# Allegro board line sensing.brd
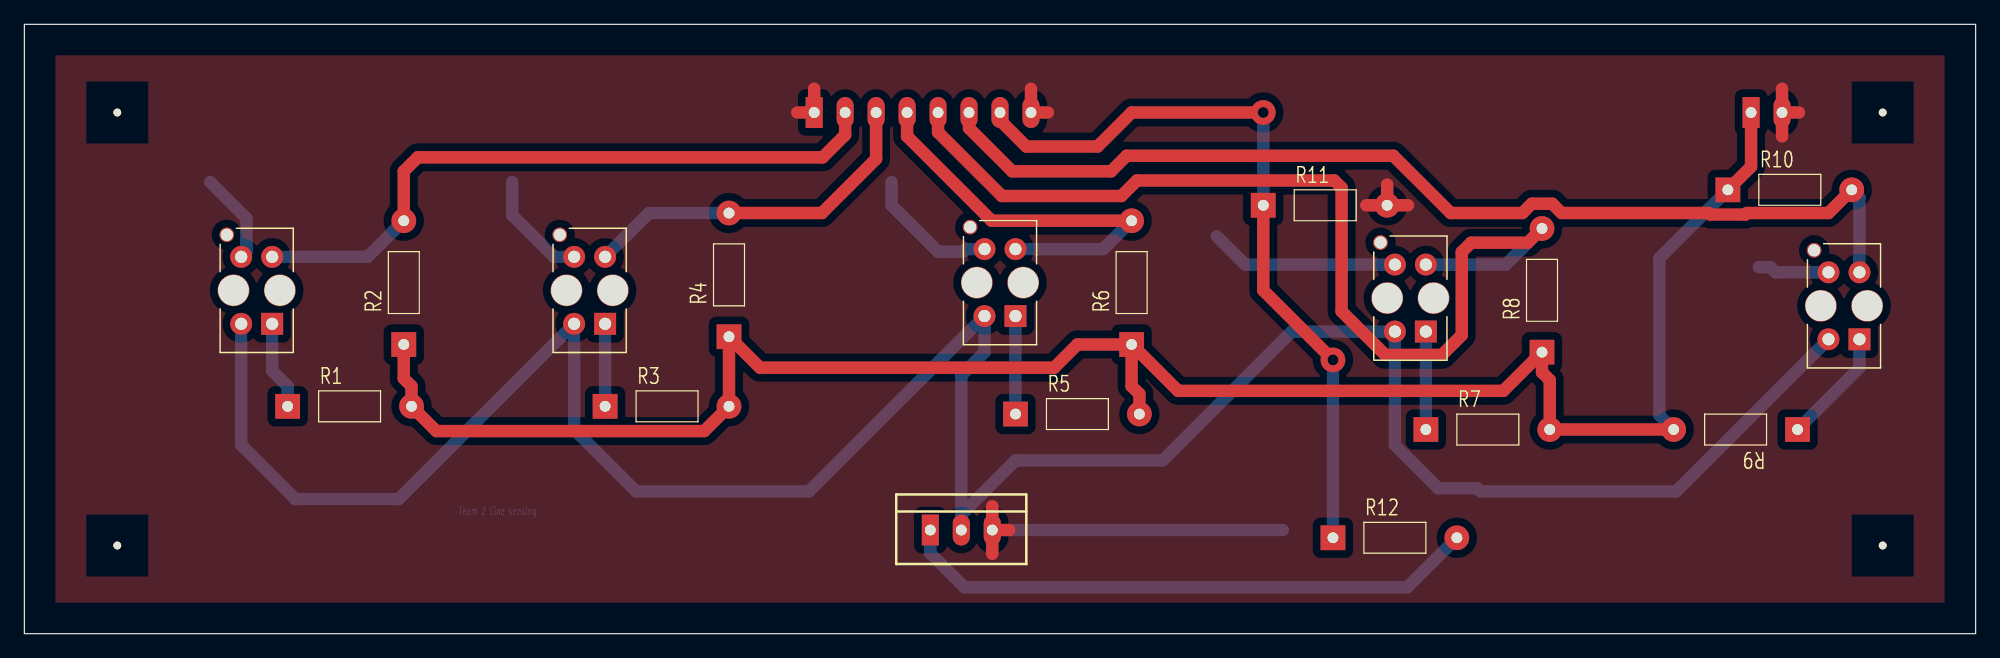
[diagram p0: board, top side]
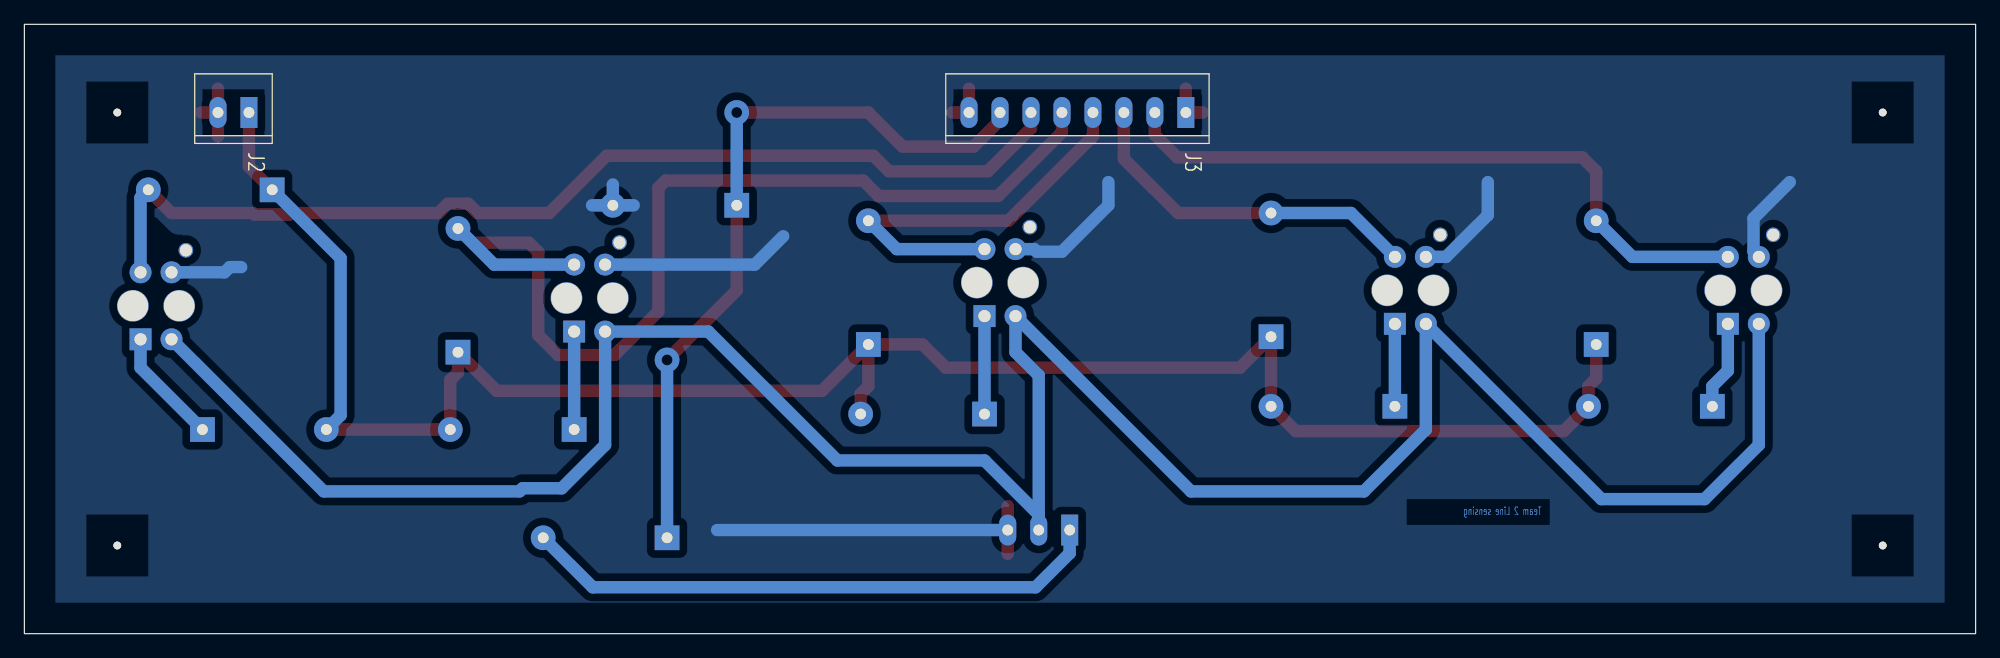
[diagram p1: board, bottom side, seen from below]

Outline 160.02 x 50.04 mm; copper layers: TOP, BOTTOM. Coordinates in mm from the lower left corner of the outline.
Outline path: rectangle 0,0 160.02,50.04

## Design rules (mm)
constraint set DEFAULT: min track width 1.016

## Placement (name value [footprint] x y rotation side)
J2  Power  [GU-MOLEX2]  141.61 42.8 270 bottom
J3  CON8  [GU-MOLEX8]  64.77 42.8 270 bottom
NOREF  -  [unnamed]  7.62 42.8 0 top
NOREF#2  -  [unnamed]  152.4 42.8 0 top
NOREF#3  -  [unnamed]  152.4 7.24 0 top
NOREF#4  -  [unnamed]  7.62 7.24 0 top
Q1  TIP121  [GU-TO220AB]  74.3 8.51 0 top
R1  200  [GU-RC400]  21.59 18.67 0 top
R2  10K  [GU-RC400]  31.12 23.75 90 top
R3  200  [GU-RC400]  47.63 18.67 0 top
R4  10K  [GU-RC400]  57.79 24.38 90 top
R5  200  [GU-RC400]  81.28 18.03 0 top
R6  10K  [GU-RC400]  90.81 23.75 90 top
R7  200  [GU-RC400]  114.94 16.76 0 top
R8  10K  [GU-RC400]  124.46 23.11 90 top
R9  200  [GU-RC400]  145.42 16.76 180 top
R10  10K  [GU-RC400]  139.7 36.45 0 top
R11  100K  [GU-RC400]  101.6 35.18 0 top
R12  Rb  [GU-RC400]  107.31 7.87 0 top
U1  TCRT5000  [VISHAY_TCRT5000]  19.05 28.19 270 top
U2  TCRT5000  [VISHAY_TCRT5000]  46.36 28.19 270 top
U3  TCRT5000  [VISHAY_TCRT5000]  80.01 28.83 270 top
U4  TCRT5000  [VISHAY_TCRT5000]  113.67 27.56 270 top
U5  TCRT5000  [VISHAY_TCRT5000]  149.23 26.92 270 top

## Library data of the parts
J2 = CON2
J3 = CON8
Q1 = 1R1001
R1-R12 = R
U1-U5 = TCRT5000

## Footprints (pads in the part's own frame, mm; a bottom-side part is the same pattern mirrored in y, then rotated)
GU-MOLEX2
  rect 2.54x1.397 hole 0.889: 1(0,0)
  oval 2.54x1.397 hole 0.889: 2(0,-2.54)
GU-MOLEX8
  rect 2.54x1.397 hole 0.889: 1(0,0)
  oval 2.54x1.397 hole 0.889: 2(0,-2.54) 3(0,-5.08) 4(0,-7.62) 5(0,-10.16) 6(0,-12.7) 7(0,-15.24) 8(0,-17.78)
GU-RC400
  rect 2.032x2.032 hole 0.889: 1(0,0)
  round 2.032 hole 0.889: 2(10.16,0)
GU-TO220AB
  rect 1.397x2.54 hole 0.889: 1(0,0)
  oval 1.397x2.54 hole 0.889: 2(2.54,0) 3(5.08,0)
unnamed
  round 0.635 hole 3.175 unplated: (0,0)
VISHAY_TCRT5000
  round 1.2 hole 1: (-4.56,-2.45)
  round 2.6 hole 2.5: (0,1.9) (0,-1.9)
  rect 1.8x1.8 hole 1: 1(2.75,1.27)
  round 1.8 hole 1: 2(2.75,-1.27) 3(-2.75,-1.27) 4(-2.75,1.27)

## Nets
3.3V: J2.1 R1.2 R2.1 R3.2 R4.1 R5.2 R6.1 R7.2 R8.1 R9.2 R10.1
GND: J2.2 J3.1 J3.8 Q1.3(E) R11.2 U1.3(EMITTER) U2.3(EMITTER) U3.3(EMITTER) U4.3(EMITTER) U5.3(EMITTER)
COLLECTOR: Q1.2 U1.2 U2.2 U3.2 U4.2 U5.2
GPIO: J3.7 R11.1 R12.1
SIGNAL 1: J3.2 R2.2 U1.4
SIGNAL 2: J3.3 R4.2 U2.4
SIGNAL 3: J3.4 R6.2 U3.4
SIGNAL 4: J3.5 R8.2 U4.4
SIGNAL 5: J3.6 R10.2 U5.4
N08690: R1.1 U1.1
N08740: Q1.1 R12.2
N09174: R3.1 U2.1
N09466: R5.1 U3.1
N13033: R7.1 U4.1
N13322: R9.1 U5.1

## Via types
v1: diameter 2.032, hole 0.889, TOP to BOTTOM, 2 vias

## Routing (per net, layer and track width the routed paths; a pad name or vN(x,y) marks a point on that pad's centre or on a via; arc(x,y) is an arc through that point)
3.3V: length 163.2
  TOP w1.016: R6.1 86.36,23.75 84.46,21.84 60.33,21.84 R4.1 R3.2 55.75,16.64 33.78,16.64 R1.2 31.75,20.32 31.12,20.95 R2.1 ; R6.1 90.81,20.32 91.44,19.68 R5.2 ; R6.1 94.62,19.94 121.28,19.94 R8.1 124.46,21.46 125.09,20.83 R7.2 135.25,16.76 ; 141.61,43.43 J2.1 141.61,38.35 R10.1
  BOTTOM w1.016: R10.1 134.09,30.84 134.09,17.93 135.25,16.76
GND: length 100.7
  TOP w1.016: 82.55,44.76 J3.8 83.93,42.8 ; 110.06,35.18 R11.2 ; R11.2 113.46,35.18 ; R11.2 111.76,36.88 ; 63.39,42.8 J3.1 64.77,44.76 ; J2.2 145.53,42.8 ; J2.2 144.15,40.84 ; J2.2 144.15,44.76 ; 79.38,8.51 80.76,8.51 ; 79.38,8.51 79.38,10.47 ; 79.38,8.51 79.38,6.55
  BOTTOM w1.016: 97.79,32.64 100.12,30.31 U4.3 ; 142.24,30.1 143.18,30.1 143.6,29.67 147.95,29.67 ; U3.3 77.2,31.58 76.99,31.37 74.93,31.37 71.12,35.18 71.12,37.08 ; 15.24,37.08 18.22,34.11 18.22,31.38 U1.3 ; 79.38,8.51 103.21,8.51 ; 40.01,37.08 40.01,34.37 43.43,30.94 45.09,30.94 ; 110.06,35.18 R11.2 ; R11.2 113.46,35.18 ; R11.2 111.76,36.88
COLLECTOR: length 207.2
  BOTTOM w1.016: 147.95,24.17 135.47,11.68 119.41,11.68 119.16,11.94 115.95,11.94 112.4,15.49 U4.2 103.93,24.81 93.34,14.22 81.28,14.22 76.84,9.78 ; U1.2 17.78,15.49 22.23,11.05 30.69,11.05 45.09,25.44 45.09,16.76 50.17,11.68 64.35,11.68 U3.2 78.74,23.11 76.84,21.21 76.84,9.78 ; 76.84,9.78 Q1.2
GPIO: length 62.2
  TOP w1.016: v1(101.6,42.8) 90.81,42.8 88.01,40 82.17,40 80.01,42.16 J3.7 80.01,43.43 ; R11.1 101.6,28.19 v1(107.31,22.48)
  BOTTOM w1.016: v1(107.31,22.48) R12.1 ; R11.1 v1(101.6,42.8)
SIGNAL 1: length 56
  TOP w1.016: 67.31,43.43 J3.2 67.31,40.96 65.47,39.12 32.26,39.12 31.12,37.97 R2.2
  BOTTOM w1.016: U1.4 28.15,30.94 R2.2
SIGNAL 2: length 30
  TOP w1.016: R4.2 65.41,34.54 69.85,38.99 J3.3 69.85,43.43
  BOTTOM w1.016: R4.2 51.22,34.54 U2.4
SIGNAL 3: length 34.4
  TOP w1.016: 72.39,43.43 J3.4 72.39,40.84 79.33,33.91 R6.2
  BOTTOM w1.016: R6.2 88.48,31.58 U3.4
SIGNAL 4: length 85.4
  TOP w1.016: R8.2 123.29,32.11 118.65,32.11 117.88,31.34 117.88,24.52 116.26,22.89 111.6,22.89 108.03,26.47 108.03,36.62 107.43,37.21 91.23,37.21 89.96,35.94 80.17,35.94 74.93,41.18 J3.5 74.93,43.43
  BOTTOM w1.016: 114.94,30.31 121.5,30.31 R8.2
SIGNAL 5: length 86.8
  TOP w1.016: 77.47,43.43 J3.6 77.47,41.51 81.01,37.97 89.12,37.97 90.39,39.24 112.27,39.24 116.97,34.54 122.86,34.54 123.62,35.31 125.3,35.31 126.06,34.54 138.14,34.54 138.26,34.42 141.14,34.42 141.26,34.54 147.95,34.54 R10.2
  BOTTOM w1.016: R10.2 150.5,35.81 U5.4
N08690: length 7.3
  BOTTOM w1.016: U1.1 20.32,21.59 21.59,20.32 R1.1
N08740: length 47.9
  BOTTOM w1.016: R12.2 113.41,3.81 77.09,3.81 74.3,6.6 Q1.1
N09174: length 6.8
  BOTTOM w1.016: R3.1 U2.1
N09466: length 8
  BOTTOM w1.016: U3.1 R5.1
N13033: length 8
  BOTTOM w1.016: 114.94,24.81 R7.1
N13322: length 9.5
  BOTTOM w1.016: R9.1 150.5,21.84 U5.1

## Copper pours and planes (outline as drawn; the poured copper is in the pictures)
GND on TOP: 2.54,47.5 157.48,47.5 157.48,2.54 2.54,2.54
GND on BOTTOM: 2.54,47.5 157.48,47.5 157.48,2.54 2.54,2.54 ; 9 cut-outs

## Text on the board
BOTTOM: Team 2 Line sensing
